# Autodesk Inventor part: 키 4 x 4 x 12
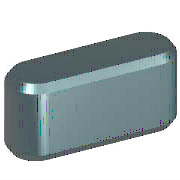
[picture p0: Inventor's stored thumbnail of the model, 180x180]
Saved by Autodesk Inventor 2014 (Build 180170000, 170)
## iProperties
IsCustomPart: 1
Created: 2012-02
Part Number: 키 4 x 4 x 12
Material: 강철, 연강
Description: 키 및 해당 키홈
Document SubType Name: Modeling
Standard: KS B 1311
Designer: mduedu
Standards Organization: KS
Language: ko-KR
Size Designation: 4 x 4 x 12
Categories: <MemberInstance><Categories><Category DisplayName="샤프트 부품" InternalName="7f7aeb1f-a693-4053-b835-cee3144e0d98" Mnemonic="SHFT"><Category DisplayName="키" Interna
Density: 1 g/cm^3
Appearance: 노란색
Author: mduedu
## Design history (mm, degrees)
workplane "Work Plane1"
workplane "Work Plane2"
sketch "스케치1"
  geometry: L1 (2, 2)-(10, 2); L2 (10, -2)-(2, -2); L3 (0, 9.4)-(0, -7.4) reference; L4 (-5, 0)-(30, 0) reference; L5 (12, 0)-(12, 7); A1 r 2 centre (2, 0) between (2, 2) and (2, -2); A2 r 2 centre (10, 0) between (10, -2) and (10, 2)
  constraints: 6 end point, 5 point on circle, 4 tangent, 3 point on line, 2 centre point, 1 horizontal, 1 parallel, 1 perpendicular
  dimensions: "d0" = 2 radius of A1 (= 0.5 x PB); "d13" = 2 radius of A2 (= 0.5 x PB); "d14" = 12 distance between parallel lines of L5 L3 (= NLG)
extrude "본체1" new body sketch "스케치1" taper "d3" = 0 deg; stored distance "d4" = 10
workplane "Work Plane3"
body "Solid1"
chamfer "모따기1" distance "d8" = 0.25 (= PHH); stored, may be unused: second distance "d9" = 0.25 (= PHH), angle "d15" = 45 deg
other parameters: "d1" = -2.5 (= -PNT), "d2" = 1.5 (= PH - PNT), "NLG" = 12 [user parameter; used in 3 equation terms], "PB" = 4 [user parameter; used in 2 equation terms], "PNT" = 2.5 [user parameter; used in 2 equation terms], "PH" = 4 [user parameter; used in 1 equation term], "PHH" = 0.25 [user parameter; used in 2 equation terms], "d10" = 0, "d16" = 0, "d17" = 0, "d18" = 0, "PLB2" = 12 (= NLG) [user parameter], "WDMAX" = 12 [user parameter], "PLB1" = 12 (= NLG) [user parameter], "RR" = 0.08 [user parameter], "PUEB" = 1.8 [user parameter]
